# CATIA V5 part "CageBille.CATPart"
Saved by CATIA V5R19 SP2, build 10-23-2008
Part number: CageBille
Definition: NONE
Nomenclature: 1
Source: Unknown
Description: PART-1-DESC
Bounding box of the stored display mesh (mm): x -15.15 to 15.15, y 0 to 36, z -15.15 to 15.15
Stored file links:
  D:\SCHOOL\FRANCE\BANC_POUTRE_EN_MOUSSE\CageBille.CATPart
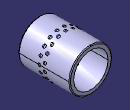
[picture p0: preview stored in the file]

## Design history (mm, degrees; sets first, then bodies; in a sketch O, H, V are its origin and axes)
Body1 "1" (main body)
  Solid1: solid without history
